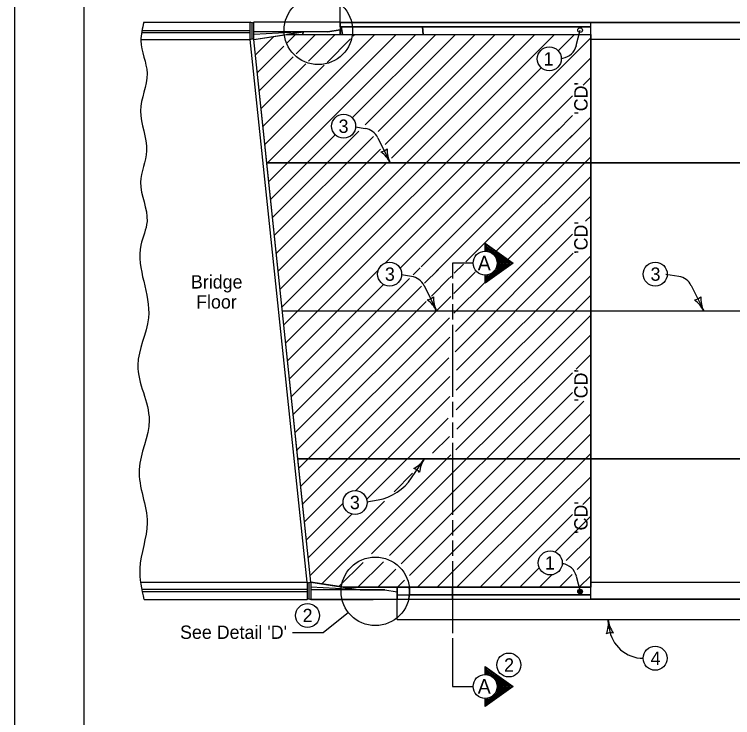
# Model space of a CAD drawing. Extents: x -2135039 to -2131695, y -2139150 to -2136566.
# Drawn here: x -2135039 to -2133962, y -2138527 to -2137471 of the extents above; entities that cross this region are included whole.
import ezdxf

# ---------------------------------------------------------------- set-up
doc = ezdxf.new("R2010")
doc.units = 0
for name, color, linetype in [('Default', 7, 'Continuous'), ('dsnDOTLogo', 7, 'Continuous'), ('Level 1', 7, 'Continuous'), ('Level 2', 7, 'Continuous'), ('Level 3', 7, 'Continuous')]:
    doc.layers.add(name, color=color, linetype=linetype)

msp = doc.modelspace()

# ---------------------------------------------------------------- linework, layer by layer
at = {"layer": 'Default'}
msp.add_line((-2134174.5, -2137483.5), (-2133249.3, -2137483.5), dxfattribs=at)
at = {"layer": 'dsnDOTLogo'}
msp.add_lwpolyline([(-2135038.9, -2139150.4), (-2131694.9, -2139150.4), (-2131694.9, -2136566.4), (-2135038.9, -2136566.4)], close=True, dxfattribs=at)
at = {"layer": 'Level 1'}
msp.add_lwpolyline([(-2134934.4, -2137035.9), (-2131799.4, -2137035.9), (-2131799.4, -2139045.9), (-2134934.4, -2139045.9)], close=True, dxfattribs=at)
at = {"layer": 'Level 2'}
for p, q in [((-2134550.3, -2137489.7), (-2134550.3, -2137452.7)), ((-2134844.8, -2137482.8), (-2134685.4, -2137482.8)), ((-2134685.4, -2137509), (-2134685.4, -2137482.8)), ((-2134682.6, -2137483.9), (-2134685.4, -2137482.8)), ((-2134682.6, -2137483.9), (-2134679.8, -2137482.8)), ((-2134682.6, -2137483.9), (-2134682.6, -2137507.8)), ((-2134679.8, -2137509), (-2134679.8, -2137482.8)), ((-2134679.8, -2137509), (-2134679.8, -2137482.8)), ((-2134550.3, -2137482.8), (-2134679.8, -2137482.8)), ((-2134550.3, -2137482.8), (-2134550.3, -2137494.3)), ((-2134550.3, -2137483.5), (-2134174.5, -2137483.5)), ((-2134174.5, -2137483.5), (-2134550.3, -2137483.5)), ((-2134550.3, -2137483.5), (-2134550.3, -2137489.7)), ((-2134174.5, -2137845.6), (-2134174.5, -2137483.5)), ((-2134174.5, -2137483.5), (-2133804.4, -2137483.5)), ((-2133804.4, -2137483.5), (-2134174.5, -2137483.5)), ((-2134174.5, -2137489.7), (-2134174.5, -2137483.5)), ((-2134847.8, -2137495.1), (-2134685.4, -2137495.1)), ((-2134568.8, -2137497.4), (-2134550.3, -2137494.3)), ((-2134550.3, -2137494.3), (-2134568.8, -2137497.4)), ((-2134550.3, -2137489.7), (-2134174.5, -2137489.7)), ((-2134549, -2137489.7), (-2134550.3, -2137494.3)), ((-2134550.3, -2137489.7), (-2134550.3, -2137489.7)), ((-2134550.3, -2137489.7), (-2134550.3, -2137494.3)), ((-2134550.3, -2137494.3), (-2134549, -2137489.7)), ((-2134549, -2137489.7), (-2134550.3, -2137489.7)), ((-2134550.3, -2137489.7), (-2134174.5, -2137489.7)), ((-2134550.3, -2137494.3), (-2134550.3, -2137501.3)), ((-2134550.3, -2137501.3), (-2134550.3, -2137494.3)), ((-2134550.3, -2137494.3), (-2134550.3, -2137494.3)), ((-2134550.3, -2137494.3), (-2134550.3, -2137501.3)), ((-2134550.3, -2137494.3), (-2134550.3, -2137494.3)), ((-2134549, -2137489.7), (-2134546.6, -2137501.3)), ((-2134426.7, -2137489.7), (-2134549, -2137489.7)), ((-2134546.6, -2137501.3), (-2134549, -2137489.7)), ((-2134426, -2137501.3), (-2134426.7, -2137489.7)), ((-2134174.5, -2137489.7), (-2134426.7, -2137489.7)), ((-2134426.7, -2137489.7), (-2134426, -2137501.3)), ((-2134174.5, -2137501.3), (-2134174.5, -2137489.7)), ((-2134848.3, -2137498.2), (-2134685.4, -2137498.2)), ((-2134568.8, -2137497.4), (-2134679.8, -2137497.4)), ((-2134605.8, -2137497.4), (-2134679.8, -2137501.3)), ((-2134679.8, -2137509), (-2134605.8, -2137497.4)), ((-2134679.8, -2137509), (-2134630.5, -2137501.3)), ((-2134677.4, -2137531.9), (-2134649.9, -2137504.3)), ((-2134663.3, -2137666.4), (-2134498.1, -2137501.3)), ((-2134660.3, -2137695.1), (-2134466.4, -2137501.3)), ((-2134657.4, -2137722), (-2134436.7, -2137501.3)), ((-2134640.5, -2137883.4), (-2134258.3, -2137501.3)), ((-2134637.6, -2137910.3), (-2134228.6, -2137501.3)), ((-2134632, -2137964), (-2134174.5, -2137506.5)), ((-2134605.8, -2137497.4), (-2134630.5, -2137501.3)), ((-2134630.5, -2137501.3), (-2134174.5, -2137501.3)), ((-2134630.5, -2137501.3), (-2134606.4, -2137501.3)), ((-2134630.5, -2137501.3), (-2134174.4, -2137501.3)), ((-2134629.9, -2137514), (-2134617.1, -2137501.3)), ((-2134616.4, -2137530.2), (-2134587.4, -2137501.3)), ((-2134605.8, -2137497.4), (-2134606.4, -2137501.3)), ((-2134606.4, -2137501.3), (-2134605.8, -2137497.4)), ((-2134606.4, -2137501.3), (-2134550.3, -2137501.3)), ((-2134568.8, -2137497.4), (-2134605.8, -2137497.4)), ((-2134597.9, -2137541.5), (-2134557.8, -2137501.3)), ((-2134550.3, -2137501.3), (-2134546.6, -2137501.3)), ((-2134546.6, -2137501.3), (-2134426, -2137501.3)), ((-2134532.2, -2137626.4), (-2134407, -2137501.3)), ((-2134530.7, -2137504), (-2134528.1, -2137501.3)), ((-2134512.7, -2137636.6), (-2134377.3, -2137501.3)), ((-2134493.3, -2137646.9), (-2134347.6, -2137501.3)), ((-2134482.6, -2137666.2), (-2134317.7, -2137501.3)), ((-2134473.4, -2137686.7), (-2134288, -2137501.3)), ((-2134426, -2137501.3), (-2134174.5, -2137501.3)), ((-2134223.3, -2137525.6), (-2134198.9, -2137501.3)), ((-2134174.4, -2137501.3), (-2134174.4, -2137694)), ((-2134849.1, -2137509), (-2134685.4, -2137509)), ((-2134685.4, -2137509), (-2134682.6, -2137507.8)), ((-2134599.8, -2138323.1), (-2134685.4, -2137509)), ((-2134679.8, -2137509), (-2134682.6, -2137507.8)), ((-2134594.3, -2138323.1), (-2134679.8, -2137509)), ((-2134660.4, -2137694), (-2134679.8, -2137509)), ((-2134569.9, -2137543.2), (-2134534.6, -2137507.8)), ((-2133804.4, -2137509), (-2134174.4, -2137509)), ((-2134174.4, -2137509), (-2134174.4, -2137694)), ((-2134674.6, -2137558.7), (-2134634.9, -2137519)), ((-2134671.8, -2137585.6), (-2134620.8, -2137534.7)), ((-2134482.3, -2137844), (-2134174.5, -2137536.2)), ((-2134218.6, -2137537.1), (-2134216.6, -2137536.8)), ((-2134669, -2137612.5), (-2134602, -2137545.5)), ((-2134666.1, -2137639.3), (-2134574.1, -2137547.3)), ((-2134634.8, -2137937.2), (-2134248.7, -2137551.1)), ((-2134186, -2137577.4), (-2134174.5, -2137565.9)), ((-2134460.5, -2137851.9), (-2134201.6, -2137593.1)), ((-2134225.5, -2137646.7), (-2134201.6, -2137622.8)), ((-2134205.8, -2137656.7), (-2134174.5, -2137625.3)), ((-2134651.8, -2137775.7), (-2134522.4, -2137646.3)), ((-2134428.7, -2137849.8), (-2134221.9, -2137643)), ((-2134654.6, -2137748.8), (-2134557.6, -2137651.8)), ((-2134649, -2137802.6), (-2134500.5, -2137654.2)), ((-2134406.1, -2137856.9), (-2134202.2, -2137653)), ((-2134361.6, -2137842.2), (-2134174.5, -2137655)), ((-2134176.2, -2137656.7), (-2134174.5, -2137655)), ((-2134646.1, -2137829.7), (-2134489.6, -2137673.2)), ((-2134316.1, -2137826.4), (-2134174.5, -2137684.7)), ((-2133249.3, -2137694), (-2134660.4, -2137694)), ((-2134174.4, -2137694), (-2134660.4, -2137694)), ((-2134643.3, -2137856.6), (-2134479.9, -2137693.1)), ((-2134174.5, -2138138.1), (-2134174.5, -2137694)), ((-2134174.4, -2137694), (-2133804.4, -2137694)), ((-2134174.4, -2138138.1), (-2134174.4, -2137694)), ((-2134174.4, -2137694), (-2133804.4, -2137694)), ((-2134298.8, -2137838.8), (-2134174.5, -2137714.4)), ((-2134377.5, -2137947.1), (-2134182.3, -2137751.9)), ((-2134188.3, -2137757.9), (-2134174.5, -2137744.1)), ((-2134182.1, -2137781.4), (-2134174.5, -2137773.8)), ((-2134377.9, -2137977.3), (-2134201.6, -2137801)), ((-2134375.7, -2138004.8), (-2134200.6, -2137829.6)), ((-2134376.5, -2138035.2), (-2134174.5, -2137833.2)), ((-2134440.9, -2137862), (-2134430.2, -2137851.4)), ((-2134379.1, -2137859.6), (-2134365.4, -2137845.9)), ((-2134174.5, -2138348.6), (-2134174.5, -2137845.6)), ((-2134629.2, -2137990.9), (-2134493, -2137854.7)), ((-2134423.8, -2137874.6), (-2134403, -2137853.9)), ((-2134373.3, -2137883.6), (-2134347.6, -2137857.8)), ((-2134623.5, -2138044.7), (-2134446.5, -2137867.7)), ((-2134413.5, -2137894), (-2134386.6, -2137867.1)), ((-2134388.7, -2137869.2), (-2134383.4, -2137863.9)), ((-2134379.7, -2137919.6), (-2134332.9, -2137872.9)), ((-2134376.1, -2138064.5), (-2134174.5, -2137862.9)), ((-2134626.3, -2138017.8), (-2134485.1, -2137876.5)), ((-2134620.7, -2138071.5), (-2134428.1, -2137878.9)), ((-2134380, -2137890.2), (-2134371.7, -2137882)), ((-2134375.4, -2138093.5), (-2134174.5, -2137892.6)), ((-2134617.9, -2138098.4), (-2134421.5, -2137902.1)), ((-2134615.1, -2138125.3), (-2134384.4, -2137894.6)), ((-2134637, -2137916), (-2134174.5, -2137916)), ((-2134174.5, -2137916), (-2132658.2, -2137916)), ((-2134612.2, -2138152.2), (-2134386.4, -2137926.3)), ((-2134376.9, -2138124.7), (-2134174.5, -2137922.3)), ((-2134609.4, -2138179), (-2134385.8, -2137955.4)), ((-2134503.3, -2138280.9), (-2134174.5, -2137952)), ((-2134606.6, -2138205.9), (-2134387.1, -2137986.4)), ((-2134196.2, -2138003.5), (-2134174.5, -2137981.7)), ((-2134476.1, -2138283.4), (-2134201.6, -2138008.9)), ((-2134603.8, -2138232.8), (-2134385.7, -2138014.7)), ((-2134526.9, -2138185.6), (-2134385.9, -2138044.6)), ((-2134458.9, -2138295.8), (-2134201.6, -2138038.6)), ((-2134446.5, -2138313.1), (-2134185, -2138051.6)), ((-2134510.6, -2138199), (-2134388.5, -2138076.9)), ((-2134434.5, -2138330.8), (-2134174.5, -2138070.8)), ((-2134411.6, -2138129.8), (-2134386.4, -2138104.5)), ((-2134404.8, -2138330.8), (-2134174.5, -2138100.5)), ((-2134251.2, -2138207), (-2134174.5, -2138130.2)), ((-2134594.2, -2138323.1), (-2134613.7, -2138138.1)), ((-2134613.7, -2138138.1), (-2134174.4, -2138138.1)), ((-2134577.9, -2138325.7), (-2134384.4, -2138132.3)), ((-2133804.4, -2138138.1), (-2134174.4, -2138138.1)), ((-2134174.4, -2138138.1), (-2134174.4, -2138323.1)), ((-2133804.4, -2138138.1), (-2134174.4, -2138138.1)), ((-2134174.4, -2138138.1), (-2134174.4, -2138330.8)), ((-2134469.4, -2138187.5), (-2134441.7, -2138159.8)), ((-2134209.1, -2138199.6), (-2134174.5, -2138164.9)), ((-2134340.4, -2138330.8), (-2134205.2, -2138195.6)), ((-2134186.4, -2138206.5), (-2134174.5, -2138194.6)), ((-2134600.9, -2138259.7), (-2134546, -2138204.7)), ((-2134595.3, -2138313.4), (-2134483.6, -2138201.7)), ((-2134375.1, -2138330.8), (-2134247, -2138202.7)), ((-2134598.1, -2138286.5), (-2134532.6, -2138221)), ((-2134310.7, -2138330.8), (-2134201.6, -2138221.7)), ((-2134228, -2138277.8), (-2134174.5, -2138224.3)), ((-2134211.1, -2138290.6), (-2134174.5, -2138254)), ((-2134523.6, -2138330.8), (-2134485.5, -2138292.8)), ((-2134194.9, -2138304.3), (-2134174.5, -2138283.9)), ((-2134552.2, -2138329.7), (-2134516, -2138293.5)), ((-2134493.9, -2138330.8), (-2134466.7, -2138303.6)), ((-2134281, -2138330.8), (-2134251.7, -2138301.5)), ((-2134217.2, -2138295.2), (-2134215.2, -2138295.6)), ((-2134251.3, -2138330.8), (-2134232.6, -2138312.1)), ((-2134221.4, -2138330.8), (-2134202.1, -2138311.5)), ((-2134191.7, -2138330.8), (-2134174.5, -2138313.6)), ((-2134849.7, -2138323.1), (-2134599.8, -2138323.1)), ((-2134599.8, -2138323.1), (-2134599.8, -2138349.3)), ((-2134599.8, -2138323.1), (-2134597.1, -2138324.3)), ((-2134594.3, -2138323.1), (-2134597.1, -2138324.3)), ((-2134597, -2138348.2), (-2134597, -2138324.3)), ((-2134594.3, -2138323.1), (-2134594.3, -2138349.3)), ((-2134594.3, -2138323.1), (-2134594.3, -2138349.3)), ((-2134594.3, -2138323.1), (-2134520.3, -2138334.7)), ((-2134544.9, -2138330.8), (-2134594.2, -2138323.1)), ((-2134594.2, -2138323.1), (-2134594.2, -2138323.1)), ((-2134464.2, -2138330.8), (-2134453.7, -2138320.3)), ((-2134174.4, -2138323.1), (-2133804.4, -2138323.1)), ((-2134848, -2138333.9), (-2134599.8, -2138333.9)), ((-2134520.3, -2138334.7), (-2134594.3, -2138330.8)), ((-2134483.2, -2138334.7), (-2134594.3, -2138334.7)), ((-2134544.9, -2138330.8), (-2134174.5, -2138330.8)), ((-2134544.9, -2138330.8), (-2134520.3, -2138334.7)), ((-2134174.4, -2138330.8), (-2134544.9, -2138330.8)), ((-2134520.3, -2138334.7), (-2134483.2, -2138334.7)), ((-2134483.2, -2138334.7), (-2134464.7, -2138337.8)), ((-2134483.2, -2138334.7), (-2134464.7, -2138337.8)), ((-2134464.7, -2138337.8), (-2134464.7, -2138330.8)), ((-2134464.7, -2138337.8), (-2134464.7, -2138330.8)), ((-2134464.7, -2138330.8), (-2134464.7, -2138337.8)), ((-2134381.8, -2138342.4), (-2134381.8, -2138330.8)), ((-2134381.8, -2138330.8), (-2134381.8, -2138342.4)), ((-2134174.5, -2138342.4), (-2134174.5, -2138330.8)), ((-2134847.6, -2138337), (-2134599.8, -2138337)), ((-2134464.7, -2138349.3), (-2134464.7, -2138337.8)), ((-2134464.7, -2138337.8), (-2134464.7, -2138337.8)), ((-2134464.7, -2138337.8), (-2134464.7, -2138337.8)), ((-2134464.7, -2138337.8), (-2134464.7, -2138337.8)), ((-2134464.7, -2138337.8), (-2134464.7, -2138348.6)), ((-2134464.7, -2138342.4), (-2134174.5, -2138342.4)), ((-2134446.4, -2138342.4), (-2134381.8, -2138342.4)), ((-2134381.8, -2138342.4), (-2134446.4, -2138342.4)), ((-2134381.8, -2138348.6), (-2134381.8, -2138342.4)), ((-2134381.8, -2138342.4), (-2134174.5, -2138342.4)), ((-2134174.5, -2138342.4), (-2134381.8, -2138342.4)), ((-2134381.8, -2138342.4), (-2134381.8, -2138348.6)), ((-2134174.5, -2138348.6), (-2134174.5, -2138342.4)), ((-2134844.5, -2138349.3), (-2134599.8, -2138349.3)), ((-2134597.1, -2138348.2), (-2134599.8, -2138349.3)), ((-2134597.1, -2138348.2), (-2134594.3, -2138349.3)), ((-2134594.3, -2138349.3), (-2134500.9, -2138349.3)), ((-2134464.7, -2138349.3), (-2134594.3, -2138349.3)), ((-2134464.7, -2138348.6), (-2134174.5, -2138348.6)), ((-2134464.7, -2138348.6), (-2134464.7, -2138348.6)), ((-2134464.7, -2138348.6), (-2134464.7, -2138348.6)), ((-2134464.7, -2138348.6), (-2134447.5, -2138348.6)), ((-2134464.7, -2138379.4), (-2134464.7, -2138349.3)), ((-2134447.5, -2138348.6), (-2134381.8, -2138348.6)), ((-2134381.8, -2138348.6), (-2134174.5, -2138348.6)), ((-2134174.5, -2138348.6), (-2133249.3, -2138348.6)), ((-2134464.7, -2138379.4), (-2134137.5, -2138379.4)), ((-2134137.5, -2138379.4), (-2133249.3, -2138379.4))]:
    msp.add_line(p, q, dxfattribs=at)
for points in [[(-2134174.4, -2137501.3), (-2134174.5, -2137501.3), (-2134174.5, -2137483.5), (-2133804.4, -2137483.5), (-2133804.4, -2137509), (-2134174.4, -2137509)], [(-2134174.4, -2138330.8), (-2134174.4, -2138323.1), (-2133804.4, -2138323.1), (-2133804.4, -2138348.6), (-2134174.5, -2138348.6), (-2134174.5, -2138330.8)]]:
    msp.add_lwpolyline(points, close=True, dxfattribs=at)
for points in [[(-2134332.9, -2137826.4), (-2134332.9, -2137814.4), (-2134290.9, -2137844.4), (-2134332.9, -2137874.4), (-2134332.9, -2137862.4)], [(-2134331.8, -2137863.6), (-2134331.9, -2137872.3), (-2134293.2, -2137844.4), (-2134331.9, -2137816.3), (-2134331.7, -2137825.5), (-2134330, -2137826), (-2134330.7, -2137819.3), (-2134295.7, -2137844.4), (-2134330.7, -2137869.8), (-2134330.3, -2137863.4), (-2134329.1, -2137863.1), (-2134329.1, -2137867.4), (-2134298.1, -2137844.3), (-2134329.2, -2137822.4), (-2134328.6, -2137826.1), (-2134327.2, -2137826.4), (-2134327.4, -2137825.2), (-2134300.7, -2137844.6), (-2134327.9, -2137865.1), (-2134326.5, -2137862.8), (-2134303.1, -2137844.8), (-2134317.5, -2137833.4), (-2134316.6, -2137835.5), (-2134305.5, -2137844.9), (-2134316.2, -2137853.1), (-2134315.2, -2137850.9), (-2134307.8, -2137845.2), (-2134315.2, -2137838.8), (-2134314.5, -2137841.6), (-2134309.7, -2137845.3), (-2134314.6, -2137849.1), (-2134314.3, -2137847.1), (-2134311.5, -2137845.4), (-2134314.2, -2137843.7), (-2134314, -2137845.5), (-2134313.1, -2137845.4)], [(-2134464.7, -2138330.8), (-2134493.9, -2138330.8), (-2134523.6, -2138330.8), (-2134544.9, -2138330.8)], [(-2134446.5, -2138330.8), (-2134464.2, -2138330.8), (-2134464.7, -2138330.8)], [(-2134381.8, -2138330.8), (-2134404.8, -2138330.8), (-2134434.5, -2138330.8), (-2134446.5, -2138330.8)], [(-2134174.5, -2138330.8), (-2134191.7, -2138330.8), (-2134192, -2138330.8), (-2134221.4, -2138330.8), (-2134251.3, -2138330.8), (-2134281, -2138330.8), (-2134310.7, -2138330.8), (-2134340.4, -2138330.8), (-2134375.1, -2138330.8), (-2134381.8, -2138330.8)], [(-2134190.7, -2138334.1), (-2134189.4, -2138334.6), (-2134187.6, -2138335.2), (-2134187.2, -2138337.1), (-2134187.5, -2138338.8), (-2134188.7, -2138340.3), (-2134190.5, -2138340.2), (-2134192.4, -2138339.9), (-2134193.3, -2138338.4), (-2134193.4, -2138336.8), (-2134192.3, -2138334.7), (-2134190.9, -2138334.6), (-2134189, -2138335), (-2134187.5, -2138336.2), (-2134187.5, -2138338), (-2134188.7, -2138339.5), (-2134190.4, -2138339.7), (-2134192.3, -2138339.3), (-2134192.6, -2138338.2), (-2134193, -2138336.9), (-2134192.1, -2138335.4), (-2134190.7, -2138335.4), (-2134189.2, -2138335.7), (-2134188, -2138336.5), (-2134188.6, -2138338.1), (-2134189.8, -2138339), (-2134191.4, -2138339.1), (-2134191.8, -2138338.2), (-2134192.3, -2138337.3), (-2134191.5, -2138336), (-2134190.3, -2138335.7), (-2134189.3, -2138336.3), (-2134189.2, -2138337.5), (-2134189.8, -2138338.3), (-2134190.8, -2138338.6), (-2134191.4, -2138338.1), (-2134191.6, -2138337.5), (-2134191.1, -2138336.6), (-2134190.3, -2138336.4), (-2134189.6, -2138336.8), (-2134189.7, -2138337.4), (-2134190.3, -2138337.9), (-2134191, -2138337.8), (-2134191, -2138337.3), (-2134190.4, -2138337)], [(-2134332.9, -2138461.7), (-2134332.9, -2138449.7), (-2134290.9, -2138479.7), (-2134332.9, -2138509.7), (-2134332.9, -2138497.7)], [(-2134331.8, -2138498.9), (-2134331.9, -2138507.6), (-2134293.2, -2138479.7), (-2134331.9, -2138451.6), (-2134331.7, -2138460.9), (-2134330, -2138461.3), (-2134330.7, -2138454.6), (-2134295.7, -2138479.7), (-2134330.7, -2138505.1), (-2134330.3, -2138498.7), (-2134329.1, -2138498.4), (-2134329.1, -2138502.7), (-2134298.1, -2138479.6), (-2134329.2, -2138457.7), (-2134328.6, -2138461.4), (-2134327.2, -2138461.8), (-2134327.4, -2138460.5), (-2134300.7, -2138480), (-2134327.9, -2138500.4), (-2134326.5, -2138498.2), (-2134303.1, -2138480.2), (-2134317.5, -2138468.7), (-2134316.6, -2138470.8), (-2134305.5, -2138480.2), (-2134316.2, -2138488.4), (-2134315.2, -2138486.2), (-2134307.8, -2138480.5), (-2134315.2, -2138474.1), (-2134314.5, -2138476.9), (-2134309.7, -2138480.6), (-2134314.6, -2138484.4), (-2134314.3, -2138482.4), (-2134311.5, -2138480.7), (-2134314.2, -2138479.1), (-2134314, -2138480.8), (-2134313.1, -2138480.7)]]:
    msp.add_lwpolyline(points, dxfattribs=at)
for centre, radius in [((-2134190.4, -2137494.7), 3.6), ((-2134236.6, -2137537.8), 18), ((-2134545.1, -2137638.9), 18), ((-2134332.9, -2137844.4), 18), ((-2134476.1, -2137860.9), 18), ((-2134077.7, -2137860.9), 18), ((-2134528, -2138203.6), 18), ((-2134235.2, -2138294.3), 18), ((-2134497.6, -2138337), 51.4), ((-2134190.4, -2138337.4), 3.6), ((-2134190.4, -2138337.4), 3.6), ((-2134599.2, -2138373.2), 18), ((-2134077.9, -2138437.4), 18), ((-2134297.4, -2138447.5), 18), ((-2134332.9, -2138479.7), 18)]:
    msp.add_circle(centre, radius, dxfattribs=at)
for centre, radius, start, end in [((-2134491.7, -2137660.6), 17.1, 278.5122, 313.9789), ((-2134515.1, -2137713.6), 44.4, 26.2455, 54.318), ((-2134435.5, -2137674.4), 44.4, 178.1731, 206.2455), ((-2134422.2, -2137882.7), 17.1, 278.5122, 313.9789), ((-2134445.6, -2137935.7), 44.4, 26.2455, 54.318), ((-2134365.9, -2137896.4), 44.4, 178.1731, 206.2455), ((-2134021.4, -2137882.7), 17.1, 278.5122, 313.9789), ((-2134044.8, -2137935.7), 44.4, 26.2455, 54.318), ((-2133965.2, -2137896.4), 44.4, 178.1731, 206.2455), ((-2134460.7, -2138113.3), 44.4, 298.0176, 326.0901), ((-2134460.7, -2138113.3), 44.4, 298.0176, 326.0901), ((-2134387, -2138162.8), 44.4, 146.0901, 174.1626), ((-2134387, -2138162.8), 44.4, 146.0901, 174.1626), ((-2134444.6, -2138169), 17.1, 38.3568, 73.8235), ((-2134444.6, -2138169), 17.1, 38.3568, 73.8235), ((-2134497.6, -2138337), 51.4, 346.9988, 6.8909), ((-2134497.6, -2138337), 51.4, 353.9745, 6.8909), ((-2134497.6, -2138337), 51.4, 346.9988, 353.9745), ((-2134192.4, -2138385), 44.4, 339.1562, 7.2287), ((-2134104.4, -2138373.8), 44.4, 187.2287, 215.3012), ((-2134143.7, -2138416.3), 17.1, 79.4954, 114.9621)]:
    msp.add_arc(centre, radius, start, end, dxfattribs=at)
msp.add_spline([(-2134844.7, -2137482.8), (-2134849.1, -2137510.5), (-2134840, -2137559.6), (-2134849.8, -2137615.8), (-2134840.6, -2137676), (-2134849.8, -2137723.1), (-2134840, -2137781.9), (-2134849.1, -2137817.2), (-2134837.8, -2137926.5), (-2134853.8, -2137997.4), (-2134836.8, -2138080.2), (-2134851.8, -2138154.1), (-2134839.8, -2138233.9), (-2134850.8, -2138302.8), (-2134844.6, -2138349.3)], degree=3, dxfattribs=at)
at = {"layer": 'Level 3'}
for p, q in [((-2134196.1, -2137517.7), (-2134190.4, -2137494.7)), ((-2134527.1, -2137639.8), (-2134512.7, -2137642.2)), ((-2134493.9, -2137656.2), (-2134475.3, -2137694)), ((-2134613.7, -2138138.1), (-2134660.4, -2137694)), ((-2134660.4, -2137694), (-2134174.4, -2137694)), ((-2134174.4, -2137694), (-2134174.4, -2137694)), ((-2134174.4, -2137694), (-2134174.4, -2138138.1)), ((-2134458.1, -2137861.7), (-2134443.2, -2137864.2)), ((-2134061.9, -2137860.9), (-2134042.4, -2137864.2)), ((-2134424.4, -2137878.2), (-2134405.8, -2137916)), ((-2134023.6, -2137878.2), (-2134005, -2137916)), ((-2134613.7, -2138138.1), (-2133249.3, -2138138.1)), ((-2134174.4, -2138138.1), (-2134613.7, -2138138.1)), ((-2134443.2, -2138166.8), (-2134423.8, -2138138.1)), ((-2134174.4, -2138138.1), (-2134174.4, -2138138.1)), ((-2134510.1, -2138202.7), (-2134493.5, -2138199.7)), ((-2134196.1, -2138314.4), (-2134190.4, -2138337.4)), ((-2134537.8, -2138368.9), (-2134575.9, -2138399.1)), ((-2134146.7, -2138392.5), (-2134148.4, -2138379.4)), ((-2134575.9, -2138399.1), (-2134621.9, -2138399.1))]:
    msp.add_line(p, q, dxfattribs=at)
for points in [[(-2134350.9, -2137844.4), (-2134381.8, -2137844.4), (-2134381.8, -2137867.5)], [(-2134381.8, -2137875.2), (-2134381.8, -2137898.3)], [(-2134381.8, -2137906.1), (-2134381.8, -2137929.2)], [(-2134381.8, -2137936.9), (-2134381.8, -2138044.8)], [(-2134381.8, -2138052.5), (-2134381.8, -2138075.7)], [(-2134381.8, -2138083.4), (-2134381.8, -2138106.5)], [(-2134381.8, -2138114.2), (-2134381.8, -2138222.2)], [(-2134381.8, -2138229.9), (-2134381.8, -2138253)], [(-2134381.8, -2138260.7), (-2134381.8, -2138283.8)], [(-2134381.8, -2138291.5), (-2134381.8, -2138399.5)], [(-2134381.8, -2138407.2), (-2134381.8, -2138430.3)], [(-2134381.8, -2138427.7), (-2134381.8, -2138479.7), (-2134350.9, -2138479.7)]]:
    msp.add_lwpolyline(points, dxfattribs=at)
msp.add_circle((-2134583.1, -2137495.1), 51.4, dxfattribs=at)
for centre, radius, start, end in [((-2134221, -2137511.5), 25.7, 279.9303, 346.0154), ((-2134517, -2137667.5), 25.7, 26.2458, 80.4677), ((-2134447.5, -2137889.6), 25.7, 26.2458, 80.4677), ((-2134046.7, -2137889.6), 25.7, 26.2458, 80.4677), ((-2134507.1, -2138123.8), 77.1, 280.1875, 326.0921), ((-2134221, -2138320.6), 25.7, 13.9846, 80.4555), ((-2134095.7, -2138386), 51.4, 187.2287, 270)]:
    msp.add_arc(centre, radius, start, end, dxfattribs=at)

# ---------------------------------------------------------------- texts
for s, height, p in [('1', 20, (-2134245.3, -2137547.9)), ('3', 20, (-2134552.7, -2137648.9)), ('A', 22, (-2134344, -2137855.4)), ('3', 20, (-2134483.2, -2137870.9)), ('3', 20, (-2134084.8, -2137870.9)), ('Bridge', 20, (-2134774.1, -2137882.5)), ('Floor', 20, (-2134766.3, -2137912.5)), ('3', 20, (-2134535.7, -2138213.6)), ('1', 20, (-2134243.2, -2138304.3)), ('2', 20, (-2134606.6, -2138383.2)), ("See Detail 'D'", 20, (-2134790.4, -2138408.3)), ('4', 20, (-2134084.6, -2138447.4)), ('2', 20, (-2134304.4, -2138457.5)), ('A', 22, (-2134344, -2138490.7))]:
    msp.add_text(s, height=height, dxfattribs=at).set_placement(p)
for p in [(-2134179.2, -2137621.6), (-2134179.2, -2137830.4), (-2134179.2, -2138052.4), (-2134179.2, -2138250.7)]:
    msp.add_text("'CD'", height=20, rotation=90, dxfattribs=at).set_placement(p)

doc.saveas('drawing.dxf')
